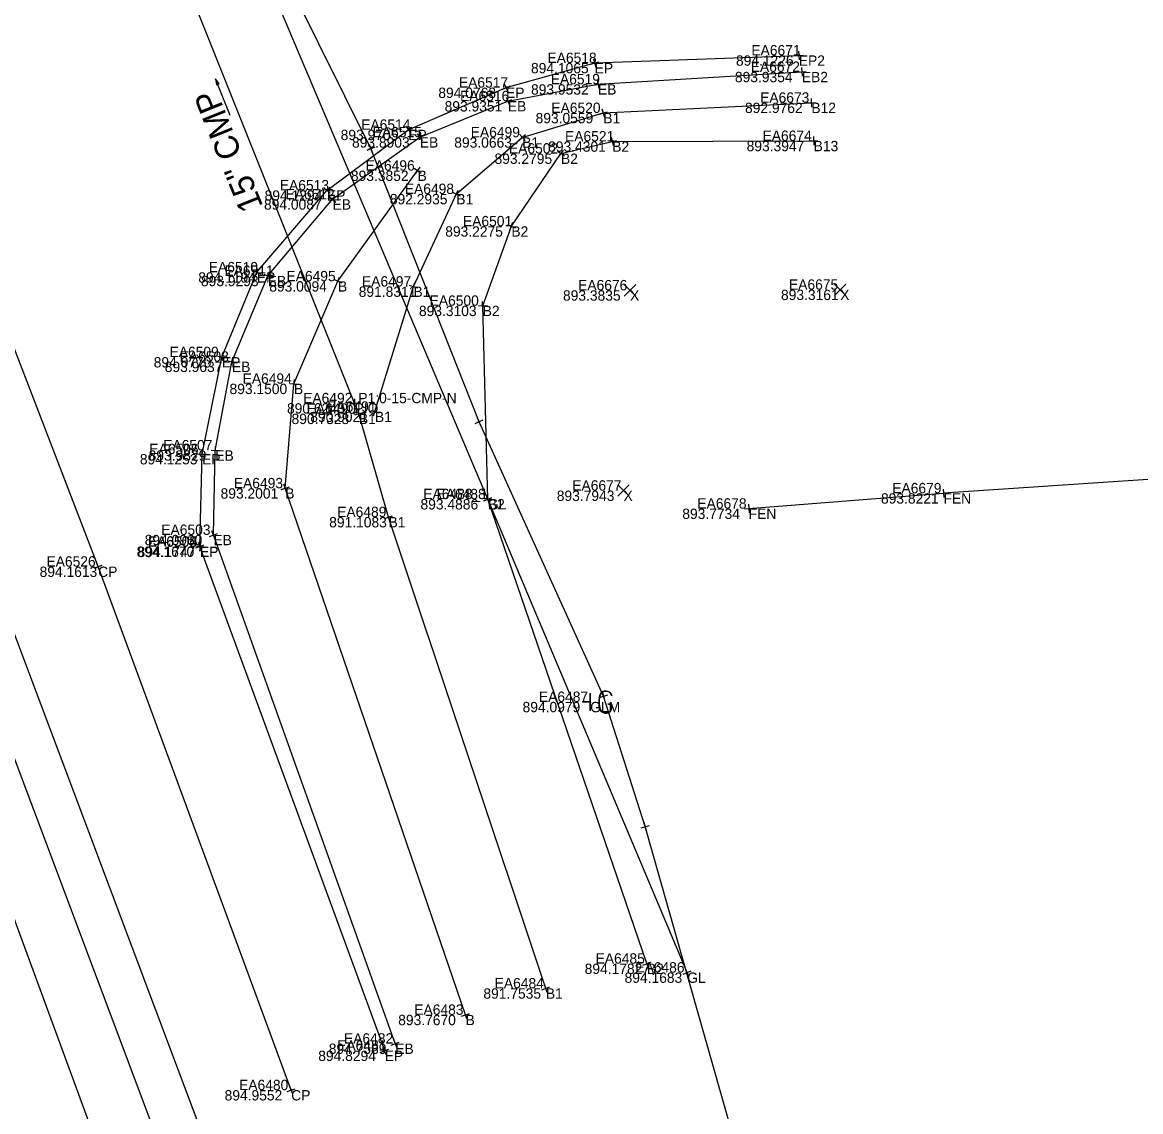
# Model space of a CAD drawing. Extents: x 179044 to 189691, y 286531 to 301257.
# Drawn here: x 180404.1 to 180533.9, y 300464.9 to 300591.3 of the extents above; entities that cross this region are included whole.
import ezdxf

# ---------------------------------------------------------------- set-up
doc = ezdxf.new("R2010")
doc.units = 0
for name, color, linetype in [('DR_X_Elev_Flow', 7, 'Continuous'), ('DR_X_Storm_Sewer', 7, 'Continuous'), ('DR_X_Text', 7, 'Continuous'), ('PV_X_COP', 7, 'Continuous'), ('PV_X_EOP', 7, 'Continuous'), ('PV_X_Shoulder_Aggregate', 7, 'Continuous'), ('RD_X_Fence', 7, 'Continuous'), ('SV_X_Break_Lines', 7, 'Continuous'), ('SV_X_Random_Point', 7, 'Continuous'), ('SV_X_Shot_Marker', 7, 'Continuous'), ('SV_X_Text_Comment', 7, 'Continuous'), ('SV_X_Text_Description', 7, 'Continuous'), ('SV_X_Text_Elevation', 7, 'Continuous'), ('SV_X_Text_Name', 7, 'Continuous'), ('UT_X_Gas', 7, 'Continuous'), ('UT_X_Gas_Cells', 7, 'Continuous')]:
    doc.layers.add(name, color=color, linetype=linetype)

msp = doc.modelspace()

# ---------------------------------------------------------------- linework, layer by layer
at = {"layer": 'DR_X_Elev_Flow'}
for p, q in [((180442.14, 300547.08), (180443.14, 300547.08)), ((180442.62, 300547.08), (180442.67, 300547.08)), ((180442.64, 300547.58), (180442.64, 300546.58)), ((180442.64, 300547.1), (180442.64, 300547.05)), ((180442.64, 300547.08), (180442.64, 300547.08)), ((180442.64, 300547.08), (180442.64, 300547.08))]:
    msp.add_line(p, q, dxfattribs=at)
at = {"layer": 'DR_X_Storm_Sewer'}
msp.add_line((180442.64, 300547.08), (180410.53, 300627.25), dxfattribs=at)
at = {"layer": 'DR_X_Text'}
msp.add_line((180428.22, 300580.46), (180426.51, 300584.73), dxfattribs=at)
msp.add_lwpolyline([(180426.63, 300584.03), (180426.91, 300584.14), (180426.51, 300584.73)], close=True, dxfattribs=at)
at = {"layer": 'PV_X_COP'}
msp.add_lwpolyline([(180435.29, 300467.37), (180412.88, 300528.12), (180394.43, 300576.01), (180387.7, 300594.07), (180373.61, 300631.85), (180356.6, 300677.34), (180322.12, 300769.7)], dxfattribs=at)
at = {"layer": 'PV_X_EOP'}
for points in [[(180446.15, 300471.95), (180424.7, 300530.45), (180424.7, 300530.42), (180424.95, 300541.18), (180427.24, 300552.43), (180431.3, 300562.27), (180439.44, 300571.78), (180448.88, 300578.81), (180460.23, 300583.7), (180470.52, 300586.56), (180494.22, 300587.44)], [(180395.24, 300541.25), (180424.93, 300462.36)]]:
    msp.add_lwpolyline(points, dxfattribs=at)
at = {"layer": 'PV_X_Shoulder_Aggregate'}
msp.add_lwpolyline([(180447.37, 300472.77), (180426.26, 300531.8), (180426.48, 300541.61), (180428.41, 300551.9), (180432.57, 300561.86), (180440.09, 300570.74), (180450.22, 300577.94), (180460.44, 300582.13), (180470.9, 300584.09), (180494.57, 300585.53)], dxfattribs=at)
at = {"layer": 'RD_X_Fence'}
for points in [[(181070.23, 300586.55), (180969.88, 300566.82), (180880.19, 300560.22), (180775.84, 300553.82), (180715.25, 300549.8), (180668.88, 300546.8), (180589.99, 300541.35), (180535.37, 300538.28), (180511.02, 300536.63)], [(180488.4, 300534.85), (180511.02, 300536.63)], [(180464.89, 300319.77), (180430.44, 300412.93), (180399.73, 300496.44)]]:
    msp.add_lwpolyline(points, dxfattribs=at)
at = {"layer": 'SV_X_Break_Lines'}
for points in [[(180445.01, 300546.1), (180449.48, 300560.62), (180454.46, 300571.36), (180462.11, 300577.93), (180471.52, 300580.76), (180495.68, 300581.95)], [(180476.58, 300482.05), (180458.12, 300535.95), (180457.52, 300558.39), (180460.85, 300567.61), (180466.61, 300576.05), (180472.56, 300577.46), (180495.94, 300577.52)], [(180455.53, 300476.11), (180434.6, 300537.21), (180435.61, 300549.34), (180440.72, 300561.23), (180449.96, 300574.07)], [(180464.85, 300479.18), (180446.59, 300533.87), (180443.15, 300545.86)], [(180397.95, 300519.64), (180420.17, 300460.57)]]:
    msp.add_lwpolyline(points, dxfattribs=at)
at = {"layer": 'SV_X_Random_Point'}
for p, q in [((180473.95, 300559.51), (180475.28, 300560.84)), ((180473.95, 300560.84), (180475.28, 300559.51)), ((180498.35, 300559.58), (180499.68, 300560.91)), ((180498.35, 300560.91), (180499.68, 300559.58)), ((180473.2, 300536.28), (180474.53, 300537.61)), ((180473.2, 300537.61), (180474.53, 300536.28))]:
    msp.add_line(p, q, dxfattribs=at)
at = {"layer": 'SV_X_Shot_Marker'}
for p, q in [((180493.72, 300587.43), (180494.72, 300587.46)), ((180494.2, 300587.94), (180494.24, 300586.94)), ((180494.22, 300587.44), (180494.22, 300587.44)), ((180470.04, 300586.42), (180471, 300586.69)), ((180470.39, 300587.04), (180470.65, 300586.07)), ((180470.52, 300586.56), (180470.52, 300586.56)), ((180494.54, 300586.03), (180494.6, 300585.03)), ((180494.07, 300585.5), (180495.07, 300585.56)), ((180494.57, 300585.53), (180494.57, 300585.53)), ((180459.77, 300583.5), (180460.69, 300583.9)), ((180460.03, 300584.16), (180460.42, 300583.24)), ((180460.23, 300583.7), (180460.23, 300583.7)), ((180470.4, 300583.99), (180471.39, 300584.18)), ((180470.8, 300584.58), (180470.99, 300583.6)), ((180470.9, 300584.09), (180470.9, 300584.09)), ((180459.98, 300581.94), (180460.9, 300582.32)), ((180460.25, 300582.59), (180460.63, 300581.66)), ((180460.44, 300582.13), (180460.44, 300582.13)), ((180495.65, 300582.45), (180495.7, 300581.45)), ((180471.04, 300580.61), (180472, 300580.9)), ((180471.37, 300581.24), (180471.66, 300580.28)), ((180471.52, 300580.76), (180471.52, 300580.76)), ((180495.18, 300581.92), (180496.18, 300581.97)), ((180495.68, 300581.95), (180495.68, 300581.95)), ((180448.48, 300578.51), (180449.28, 300579.11)), ((180448.58, 300579.21), (180449.18, 300578.41)), ((180448.88, 300578.81), (180448.88, 300578.81)), ((180449.81, 300577.65), (180450.63, 300578.23)), ((180449.93, 300578.35), (180450.51, 300577.54)), ((180461.73, 300577.61), (180462.49, 300578.26)), ((180461.79, 300578.31), (180462.44, 300577.55)), ((180444.74, 300576.18), (180444.37, 300577.11)), ((180450.22, 300577.94), (180450.22, 300577.94)), ((180462.11, 300577.93), (180462.11, 300577.93)), ((180472.08, 300577.35), (180473.05, 300577.58)), ((180472.45, 300577.95), (180472.68, 300576.97)), ((180472.56, 300577.46), (180472.56, 300577.46)), ((180495.44, 300577.52), (180496.44, 300577.52)), ((180495.94, 300578.02), (180495.95, 300577.02)), ((180495.94, 300577.52), (180495.94, 300577.52)), ((180444.09, 300576.46), (180445.02, 300576.83)), ((180444.55, 300576.64), (180444.55, 300576.64)), ((180466.2, 300576.33), (180467.03, 300575.77)), ((180466.33, 300575.64), (180466.9, 300576.46)), ((180466.61, 300576.05), (180466.61, 300576.05)), ((180449.56, 300574.36), (180450.37, 300573.78)), ((180449.67, 300573.67), (180450.26, 300574.48)), ((180449.96, 300574.07), (180449.96, 300574.07)), ((180439.06, 300572.1), (180439.82, 300571.45)), ((180439.12, 300571.4), (180439.77, 300572.16)), ((180439.44, 300571.78), (180439.44, 300571.78)), ((180454.25, 300570.9), (180454.67, 300571.81)), ((180439.71, 300571.07), (180440.47, 300570.42)), ((180439.77, 300570.36), (180440.41, 300571.13)), ((180440.09, 300570.74), (180440.09, 300570.74)), ((180454, 300571.57), (180454.91, 300571.15)), ((180454.46, 300571.36), (180454.46, 300571.36)), ((180460.38, 300567.78), (180461.32, 300567.44)), ((180460.68, 300567.14), (180461.02, 300568.08)), ((180460.85, 300567.61), (180460.85, 300567.61)), ((180431.11, 300561.81), (180431.49, 300562.73)), ((180430.83, 300562.46), (180431.76, 300562.08)), ((180431.3, 300562.27), (180431.3, 300562.27)), ((180432.11, 300562.05), (180433.03, 300561.66)), ((180432.38, 300561.39), (180432.76, 300562.32)), ((180432.57, 300561.86), (180432.57, 300561.86)), ((180440.26, 300561.43), (180441.18, 300561.04)), ((180440.52, 300560.78), (180440.91, 300561.69)), ((180440.72, 300561.23), (180440.72, 300561.23)), ((180449, 300560.76), (180449.96, 300560.47)), ((180449.33, 300560.14), (180449.63, 300561.09)), ((180449.48, 300560.62), (180449.48, 300560.62)), ((180457.54, 300557.89), (180457.51, 300558.89)), ((180457.02, 300558.37), (180458.02, 300558.4)), ((180457.52, 300558.39), (180457.52, 300558.39)), ((180426.75, 300552.53), (180427.73, 300552.33)), ((180427.14, 300551.94), (180427.34, 300552.92)), ((180427.24, 300552.43), (180427.24, 300552.43)), ((180428.31, 300551.41), (180428.5, 300552.39)), ((180427.92, 300551.99), (180428.9, 300551.81)), ((180428.41, 300551.9), (180428.41, 300551.9)), ((180435.57, 300548.84), (180435.66, 300549.83)), ((180435.12, 300549.38), (180436.11, 300549.29)), ((180435.61, 300549.34), (180435.61, 300549.34)), ((180442.67, 300545.73), (180443.63, 300546)), ((180443.29, 300545.38), (180443.01, 300546.34)), ((180443.15, 300545.86), (180443.15, 300545.86)), ((180444.53, 300546.25), (180445.49, 300545.96)), ((180444.86, 300545.63), (180445.16, 300546.58)), ((180445.01, 300546.1), (180445.01, 300546.1)), ((180456.65, 300544.72), (180457.56, 300545.14)), ((180457.31, 300544.47), (180456.9, 300545.38)), ((180457.1, 300544.93), (180457.1, 300544.93)), ((180426.47, 300541.11), (180426.5, 300542.11)), ((180424.45, 300541.19), (180425.45, 300541.17)), ((180424.94, 300540.68), (180424.97, 300541.68)), ((180424.95, 300541.18), (180424.95, 300541.18)), ((180425.98, 300541.62), (180426.98, 300541.6)), ((180426.48, 300541.61), (180426.48, 300541.61)), ((180434.13, 300537.05), (180435.08, 300537.37)), ((180434.76, 300536.74), (180434.44, 300537.68)), ((180434.6, 300537.21), (180434.6, 300537.21)), ((180510.52, 300536.59), (180511.52, 300536.67)), ((180510.98, 300537.12), (180511.06, 300536.13)), ((180511.02, 300536.63), (180511.02, 300536.63)), ((180457.65, 300535.78), (180458.59, 300536.11)), ((180457.66, 300535.75), (180458.58, 300536.14)), ((180458.32, 300535.48), (180457.93, 300536.41)), ((180458.28, 300535.47), (180457.96, 300536.42)), ((180458.12, 300535.95), (180458.12, 300535.95)), ((180458.12, 300535.95), (180458.12, 300535.95)), ((180488.36, 300535.35), (180488.44, 300534.35)), ((180446.11, 300533.71), (180447.06, 300534.03)), ((180446.75, 300533.4), (180446.43, 300534.34)), ((180487.9, 300534.81), (180488.89, 300534.89)), ((180488.4, 300534.85), (180488.4, 300534.85)), ((180446.59, 300533.87), (180446.59, 300533.87)), ((180425.79, 300531.63), (180426.73, 300531.97)), ((180426.43, 300531.33), (180426.09, 300532.27)), ((180426.26, 300531.8), (180426.26, 300531.8)), ((180425.2, 300530.37), (180424.2, 300530.48)), ((180424.23, 300530.28), (180425.17, 300530.63)), ((180424.87, 300529.98), (180424.53, 300530.92)), ((180424.75, 300530.92), (180424.64, 300529.92)), ((180424.7, 300530.45), (180424.7, 300530.45)), ((180424.7, 300530.42), (180424.7, 300530.42)), ((180412.41, 300527.95), (180413.35, 300528.3)), ((180413.05, 300527.65), (180412.7, 300528.59)), ((180412.88, 300528.12), (180412.88, 300528.12)), ((180471.08, 300512.94), (180472.04, 300513.25)), ((180471.71, 300512.62), (180471.41, 300513.57)), ((180471.56, 300513.1), (180471.56, 300513.1)), ((180475.91, 300497.81), (180476.87, 300498.08)), ((180476.53, 300497.47), (180476.25, 300498.43)), ((180476.39, 300497.95), (180476.39, 300497.95)), ((180476.11, 300481.89), (180477.06, 300482.21)), ((180476.75, 300481.58), (180476.42, 300482.52)), ((180476.58, 300482.05), (180476.58, 300482.05)), ((180480.81, 300480.83), (180481.73, 300481.21)), ((180481.46, 300480.56), (180481.07, 300481.48)), ((180481.27, 300481.02), (180481.27, 300481.02)), ((180465.01, 300478.71), (180464.69, 300479.66)), ((180464.37, 300479.02), (180465.32, 300479.34)), ((180464.85, 300479.18), (180464.85, 300479.18)), ((180455.06, 300475.95), (180456, 300476.28)), ((180455.69, 300475.64), (180455.37, 300476.59)), ((180455.53, 300476.11), (180455.53, 300476.11)), ((180447.54, 300472.3), (180447.2, 300473.24)), ((180445.68, 300471.78), (180446.62, 300472.12)), ((180446.32, 300471.48), (180445.97, 300472.42)), ((180446.15, 300471.95), (180446.15, 300471.95)), ((180446.9, 300472.6), (180447.84, 300472.94)), ((180447.37, 300472.77), (180447.37, 300472.77)), ((180435.47, 300466.9), (180435.12, 300467.84)), ((180434.82, 300467.2), (180435.76, 300467.54)), ((180435.29, 300467.37), (180435.29, 300467.37))]:
    msp.add_line(p, q, dxfattribs=at)
at = {"layer": 'UT_X_Gas'}
for points in [[(180490.47, 300448.38), (180476.39, 300497.95), (180471.56, 300513.1), (180457.1, 300544.93), (180444.55, 300576.64), (180429.4, 300607.12), (180413.67, 300639.28), (180388.52, 300702.94)], [(180481.27, 300481.02), (180458.12, 300535.95), (180424.1, 300616.25)]]:
    msp.add_lwpolyline(points, dxfattribs=at)
at = {"layer": 'UT_X_Gas_Cells'}
for p, q in [((180470, 300511.42), (180470, 300513.42)), ((180470.05, 300511.39), (180470.05, 300513.39)), ((180470, 300512.42), (180469.05, 300512.42)), ((180470.05, 300512.39), (180469.1, 300512.39))]:
    msp.add_line(p, q, dxfattribs=at)
for points in [[(180472.47, 300513.17), (180472.45, 300513.27), (180472.4, 300513.37), (180472.3, 300513.47), (180472.16, 300513.58), (180472.06, 300513.62), (180471.98, 300513.64), (180471.86, 300513.66), (180471.63, 300513.66), (180471.53, 300513.64), (180471.47, 300513.62), (180471.39, 300513.58), (180471.23, 300513.47), (180471.14, 300513.33), (180471.08, 300513.17), (180471.04, 300512.96), (180471, 300512.64), (180471, 300512.23), (180471.02, 300511.89), (180471.1, 300511.64), (180471.21, 300511.4), (180471.31, 300511.32), (180471.43, 300511.24), (180471.65, 300511.16), (180471.86, 300511.16), (180472.08, 300511.2), (180472.16, 300511.24), (180472.24, 300511.28), (180472.32, 300511.36), (180472.4, 300511.48), (180472.47, 300511.66), (180472.47, 300512.15), (180472.06, 300512.15)], [(180472.53, 300513.14), (180472.51, 300513.24), (180472.45, 300513.34), (180472.35, 300513.44), (180472.22, 300513.56), (180472.12, 300513.6), (180472.04, 300513.61), (180471.92, 300513.63), (180471.68, 300513.63), (180471.59, 300513.61), (180471.53, 300513.6), (180471.45, 300513.56), (180471.29, 300513.44), (180471.19, 300513.3), (180471.13, 300513.14), (180471.09, 300512.93), (180471.05, 300512.61), (180471.05, 300512.2), (180471.07, 300511.86), (180471.15, 300511.61), (180471.27, 300511.37), (180471.37, 300511.29), (180471.49, 300511.21), (180471.7, 300511.13), (180471.92, 300511.13), (180472.14, 300511.17), (180472.22, 300511.21), (180472.29, 300511.25), (180472.37, 300511.33), (180472.45, 300511.45), (180472.53, 300511.63), (180472.53, 300512.12), (180472.12, 300512.12)]]:
    msp.add_lwpolyline(points, dxfattribs=at)

# ---------------------------------------------------------------- texts
at = {"layer": 'DR_X_Text'}
msp.add_text('15" CMP', height=2.8, rotation=111.8323, dxfattribs=at).set_placement((180432.06, 300569.94))
at = {"layer": 'SV_X_Text_Comment'}
for s, height, p in [('EP2', 1.2, (180494.22, 300586.24)), ('EP', 1.2, (180470.52, 300585.36)), ('EB2', 1.2, (180494.57, 300584.33)), ('EP', 1.2, (180460.23, 300582.5)), ('EB', 1.2, (180470.9, 300582.89)), ('EB', 1.2, (180460.44, 300580.93)), ('B1', 1.2, (180471.52, 300579.56)), ('B12', 1.2, (180495.68, 300580.75)), ('EP', 1.2, (180448.88, 300577.61)), ('EB', 1.2, (180450.22, 300576.74)), ('B1', 1.2, (180462.11, 300576.73)), ('B2', 1.2, (180472.56, 300576.26)), ('B13', 1.2, (180495.94, 300576.32)), ('GL', 0.06, (180444.55, 300576.58)), ('B2', 1.2, (180466.61, 300574.85)), ('B', 1.2, (180449.96, 300572.87)), ('EP', 1.2, (180439.44, 300570.58)), ('EB', 1.2, (180440.09, 300569.54)), ('B1', 1.2, (180454.46, 300570.16)), ('B2', 1.2, (180460.85, 300566.41)), ('EP', 1.2, (180431.3, 300561.07)), ('EB', 1.2, (180432.57, 300560.66)), ('B', 1.2, (180440.72, 300560.03)), ('B1', 1.2, (180449.48, 300559.42)), ('X', 1.2, (180474.62, 300558.98)), ('X', 1.2, (180499.02, 300559.05)), ('B2', 1.2, (180457.52, 300557.19)), ('EP', 1.2, (180427.24, 300551.23)), ('EB', 1.2, (180428.41, 300550.7)), ('B', 1.2, (180435.61, 300548.14)), ('P1=0-15-CMP-N', 0.06, (180442.64, 300547.02)), ('PIO', 1.2, (180442.64, 300545.88)), ('B1', 1.2, (180443.15, 300544.66)), ('B1', 1.2, (180445.01, 300544.9)), ('GL', 0.06, (180457.1, 300544.87)), ('EP', 1.2, (180424.95, 300539.98)), ('EB', 1.2, (180426.48, 300540.41)), ('B', 1.2, (180434.6, 300536.01)), ('X', 1.2, (180473.87, 300535.74)), ('FEN', 1.2, (180511.02, 300535.43)), ('GL', 1.2, (180458.12, 300534.75)), ('B2', 1.2, (180458.12, 300534.75)), ('FEN', 1.2, (180488.4, 300533.65)), ('B1', 1.2, (180446.59, 300532.67)), ('EB', 1.2, (180426.26, 300530.6)), ('EP', 1.2, (180424.7, 300529.25)), ('EP', 1.2, (180424.7, 300529.22)), ('CP', 1.2, (180412.88, 300526.92)), ('GLM', 0.06, (180470.05, 300512.33)), ('GLM', 1.2, (180470, 300511.22)), ('GL', 0.06, (180471.56, 300513.04)), ('GL', 0.06, (180476.39, 300497.89)), ('B2', 1.2, (180476.58, 300480.85)), ('GL', 1.2, (180481.27, 300479.82)), ('B1', 1.2, (180464.85, 300477.98)), ('B', 1.2, (180455.53, 300474.91)), ('EP', 1.2, (180446.15, 300470.75)), ('EB', 1.2, (180447.37, 300471.57)), ('CP', 1.2, (180435.29, 300466.17))]:
    msp.add_text(s, height=height, dxfattribs=at).set_placement(p)
at = {"layer": 'SV_X_Text_Description'}
for s, height in [(' P1:0-15-CMP-N', 1.2), ('P1= 0-15-CMP-N', 0.06)]:
    msp.add_text(s, height=height, dxfattribs=at).set_placement((180442.64, 300547.08))
at = {"layer": 'SV_X_Text_Elevation'}
for s, height, p in [('894.1226', 1.2, (180486.92, 300586.24)), ('894.1065', 1.2, (180463.13, 300585.36)), ('893.9354', 1.2, (180486.8, 300584.33)), ('894.0768', 1.2, (180452.37, 300582.5)), ('893.9532', 1.2, (180463.13, 300582.89)), ('893.9351', 1.2, (180453.1, 300580.93)), ('893.0559', 1.2, (180463.66, 300579.56)), ('892.9762', 1.2, (180487.97, 300580.75)), ('893.9705', 1.2, (180441.03, 300577.61)), ('893.8903', 1.2, (180442.35, 300576.74)), ('893.0663', 1.2, (180454.22, 300576.73)), ('893.4301', 1.2, (180465.12, 300576.26)), ('893.3947', 1.2, (180488.16, 300576.32)), ('893.9830', 0.06, (180444.16, 300576.58)), ('893.2795', 1.2, (180458.89, 300574.85)), ('893.3852', 1.2, (180442.22, 300572.87)), ('894.1294', 1.2, (180432.2, 300570.58)), ('894.0087', 1.2, (180432.13, 300569.54)), ('892.2935', 1.2, (180446.74, 300570.16)), ('893.2275', 1.2, (180453.17, 300566.41)), ('894.1194', 1.2, (180424.5, 300561.07)), ('893.9293', 1.2, (180424.81, 300560.66)), ('893.0094', 1.2, (180432.74, 300560.03)), ('891.8311', 1.2, (180443.13, 300559.42)), ('893.3835', 1.2, (180466.84, 300558.98)), ('893.3161', 1.2, (180492.15, 300559.05)), ('893.3103', 1.2, (180450.12, 300557.19)), ('894.0770', 1.2, (180419.33, 300551.23)), ('893.9637', 1.2, (180420.61, 300550.7)), ('893.1500', 1.2, (180428.13, 300548.14)), ('890.6243', 1.2, (180434.8, 300545.88)), ('890.62', 0.06, (180442.36, 300547.02)), ('890.7328', 1.2, (180435.33, 300544.66)), ('890.9021', 1.2, (180437.5, 300544.9)), ('893.4610', 0.06, (180456.73, 300544.87)), ('894.1253', 1.2, (180417.72, 300539.98)), ('893.9829', 1.2, (180418.74, 300540.41)), ('893.2001', 1.2, (180427.09, 300536.01)), ('893.7943', 1.2, (180466.12, 300535.74)), ('893.8221', 1.2, (180503.76, 300535.43)), ('893.4886', 1.2, (180450.3, 300534.75)), ('893.4886', 1.2, (180450.3, 300534.75)), ('893.7734', 1.2, (180480.69, 300533.65)), ('891.1083', 1.2, (180439.7, 300532.67)), ('894.0960', 1.2, (180418.28, 300530.6)), ('894.1670', 1.2, (180417.34, 300529.25)), ('894.1747', 1.2, (180417.45, 300529.22)), ('894.1613', 1.2, (180406.08, 300526.92)), ('894.0979', 1.2, (180462.15, 300511.22)), ('893.8340', 0.06, (180469.66, 300512.33)), ('893.8610', 0.06, (180471.19, 300513.04)), ('894.0520', 0.06, (180475.99, 300497.89)), ('894.1782', 1.2, (180469.36, 300480.85)), ('894.1683', 1.2, (180473.99, 300479.82)), ('891.7535', 1.2, (180457.6, 300477.98)), ('893.7670', 1.2, (180447.71, 300474.91)), ('894.8294', 1.2, (180438.43, 300470.75)), ('894.7589', 1.2, (180439.65, 300471.57)), ('894.9552', 1.2, (180427.56, 300466.17))]:
    msp.add_text(s, height=height, dxfattribs=at).set_placement(p)
at = {"layer": 'SV_X_Text_Name'}
for s, height, p in [('EA6671', 1.2, (180488.71, 300587.44)), ('EA6518', 1.2, (180465.04, 300586.56)), ('EA6672', 1.2, (180488.64, 300585.53)), ('EA6517', 1.2, (180454.76, 300583.7)), ('EA6519', 1.2, (180465.42, 300584.09)), ('EA6516', 1.2, (180454.89, 300582.13)), ('EA6673', 1.2, (180489.73, 300581.95)), ('EA6520', 1.2, (180465.49, 300580.76)), ('EA6514', 1.2, (180443.42, 300578.81)), ('EA6515', 1.2, (180444.75, 300577.94)), ('EA6499', 1.2, (180456.13, 300577.93)), ('EA6521', 1.2, (180467.08, 300577.46)), ('EA6674', 1.2, (180490.01, 300577.52)), ('EA6502', 1.2, (180460.57, 300576.05)), ('SV5039', 0.06, (180444.25, 300576.64)), ('EA6496', 1.2, (180443.92, 300574.07)), ('EA6513', 1.2, (180433.97, 300571.78)), ('EA6512', 1.2, (180434.63, 300570.74)), ('EA6498', 1.2, (180448.48, 300571.36)), ('EA6501', 1.2, (180455.23, 300567.61)), ('EA6510', 1.2, (180425.72, 300562.27)), ('EA6511', 1.2, (180427.54, 300561.86)), ('EA6495', 1.2, (180434.74, 300561.23)), ('EA6497', 1.2, (180443.51, 300560.62)), ('EA6676', 1.2, (180468.6, 300560.18)), ('EA6675', 1.2, (180493.08, 300560.25)), ('EA6500', 1.2, (180451.36, 300558.39)), ('EA6509', 1.2, (180421.17, 300552.43)), ('EA6508', 1.2, (180422.34, 300551.9)), ('EA6494', 1.2, (180429.65, 300549.34)), ('EA6492', 1.2, (180436.68, 300547.08)), ('EA6490', 1.2, (180437.08, 300545.86)), ('EA6491', 1.2, (180439.48, 300546.1)), ('EA6492', 0.06, (180442.35, 300547.08)), ('SV5038', 0.06, (180456.8, 300544.93)), ('EA6506', 1.2, (180418.82, 300541.18)), ('EA6507', 1.2, (180420.43, 300541.61)), ('EA6493', 1.2, (180428.63, 300537.21)), ('EA6677', 1.2, (180467.92, 300536.94)), ('EA6488_1', 1.2, (180450.63, 300535.95)), ('EA6488', 1.2, (180452.16, 300535.95)), ('EA6679', 1.2, (180505.07, 300536.63)), ('EA6678', 1.2, (180482.44, 300534.85)), ('EA6489', 1.2, (180440.63, 300533.87)), ('EA6503', 1.2, (180420.21, 300531.8)), ('EA6505', 1.2, (180418.64, 300530.42)), ('EA6504', 1.2, (180418.65, 300530.45)), ('EA6526', 1.2, (180406.88, 300528.12)), ('EA6487', 1.2, (180464.05, 300512.42)), ('SV5037', 0.06, (180469.75, 300512.39)), ('SV5036', 0.06, (180471.25, 300513.1)), ('SV5035', 0.06, (180476.09, 300497.95)), ('EA6485', 1.2, (180470.63, 300482.05)), ('EA6486', 1.2, (180475.24, 300481.02)), ('EA6484', 1.2, (180458.91, 300479.18)), ('EA6483', 1.2, (180449.58, 300476.11)), ('EA6481', 1.2, (180440.63, 300471.95)), ('EA6482', 1.2, (180441.42, 300472.77)), ('EA6480', 1.2, (180429.24, 300467.37))]:
    msp.add_text(s, height=height, dxfattribs=at).set_placement(p)

doc.saveas('drawing.dxf')
